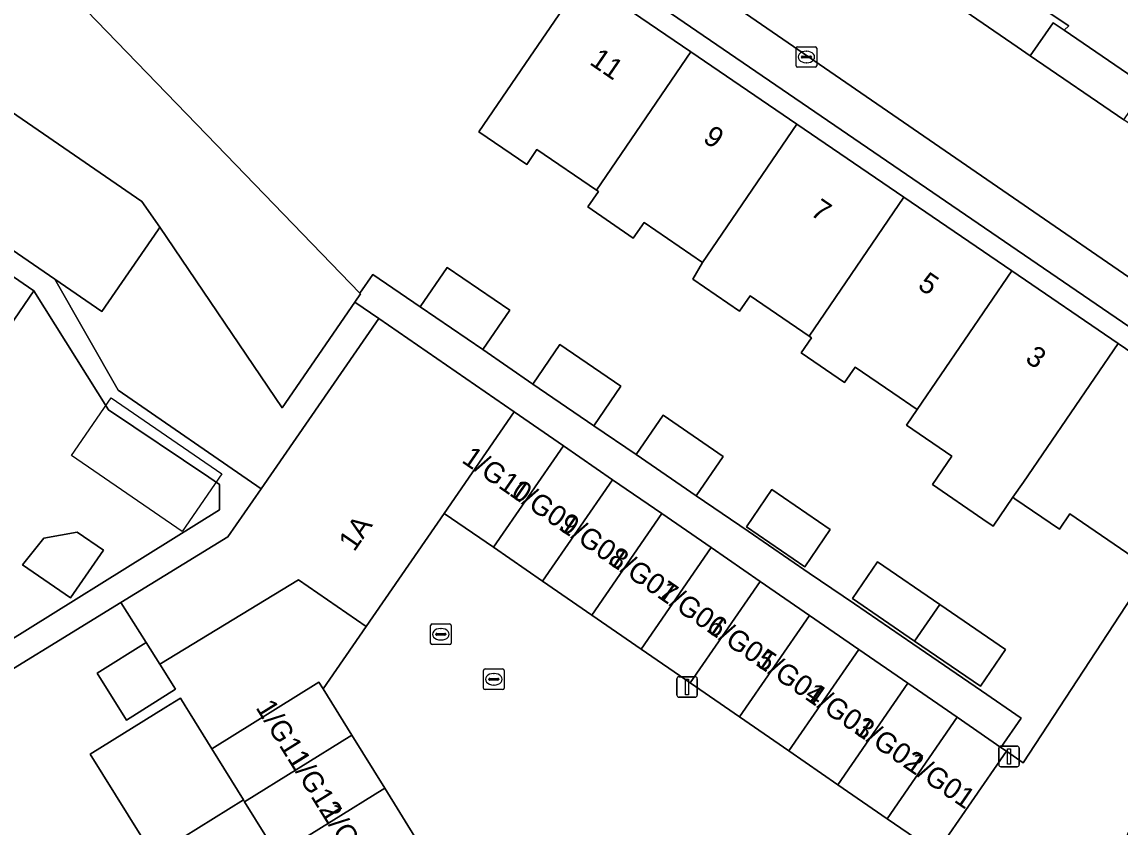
# Model space of a CAD drawing. Extents: x 160023 to 161302, y 384750 to 385707.
# Drawn here: x 160069.8 to 160123.2, y 385310.5 to 385349.6 of the extents above; entities that cross this region are included whole.
import ezdxf

# ---------------------------------------------------------------- set-up
doc = ezdxf.new("R2010")
doc.units = 0
for name, color, linetype in [('IMGEO_Erf', 7, 'Continuous'), ('IMGEO_Kolk', 7, 'Continuous'), ('IMGEO_Lichtmast', 7, 'Continuous'), ('IMGEO_Pand', 7, 'Continuous'), ('IMGEO_Pand_nummerreeks', 7, 'Continuous'), ('IMGEO_Pand_vergunning_verleend', 7, 'Continuous'), ('IMGEO_Rijbaan_lokaal_open', 7, 'Continuous'), ('IMGEO_Rioolput', 7, 'Continuous'), ('IMGEO_Voetpad_open', 7, 'Continuous')]:
    doc.layers.add(name, color=color, linetype=linetype)

msp = doc.modelspace()

# ---------------------------------------------------------------- linework, layer by layer
at = {"layer": 'IMGEO_Erf'}
for points in [[(160093.406, 385374.95), (160103.841, 385367.794), (160103.323, 385367.037), (160102.919, 385366.448), (160100.498, 385362.918), (160105.594, 385359.428), (160120.662, 385349.43), (160120.442, 385349.221), (160124.446, 385346.473), (160126.203, 385345.256), (160126.296, 385345.192), (160149.901, 385329.017), (160154.104, 385326.136), (160157.93, 385334.826), (160155.989, 385335.681), (160153.709, 385336.675), (160151.041, 385330.714), (160139.497, 385338.47), (160150.705, 385363.58)], [(160067.626, 385355.673), (160079.267, 385343.639), (160086.233, 385336.432), (160086.859, 385337.347), (160089.163, 385335.77), (160090.474, 385337.685), (160093.507, 385335.608), (160092.196, 385333.693), (160094.638, 385332.021), (160095.948, 385333.937), (160098.91, 385331.91), (160097.599, 385329.995), (160099.648, 385328.591), (160100.959, 385330.506), (160103.882, 385328.505), (160102.571, 385326.59), (160105.09, 385324.865), (160108.053, 385322.837), (160110.247, 385321.335), (160113.085, 385319.392), (160116.428, 385317.104), (160118.35, 385315.789), (160117.368, 385314.364), (160117.632, 385314.182), (160118.455, 385313.614), (160129.62, 385330.68), (160087.038, 385359.824)], [(160123.798, 385323.607), (160120.717, 385325.711), (160120.211, 385324.97), (160118.047, 385326.448), (160117.949, 385326.515), (160116.995, 385325.118), (160116.493, 385325.461), (160114.04, 385327.136), (160114.982, 385328.515), (160112.778, 385330.02), (160113.298, 385330.781), (160112.117, 385331.587), (160110.286, 385332.837), (160109.775, 385332.089), (160107.661, 385333.533), (160108.163, 385334.267), (160108.045, 385334.347), (160105.183, 385336.303), (160104.675, 385335.56), (160102.399, 385337.115), (160102.876, 385337.933), (160100.032, 385339.876), (160099.511, 385339.114), (160097.301, 385340.623), (160097.817, 385341.378), (160097.716, 385341.447), (160094.832, 385343.417), (160094.335, 385342.688), (160092.004, 385344.28), (160094.271, 385347.599), (160097.091, 385351.727), (160102.305, 385348.166), (160107.46, 385344.645), (160112.655, 385341.096), (160117.897, 385337.515), (160123.055, 385333.992), (160128.399, 385330.342)], [(160082.231, 385309.145), (160080.632, 385311.722), (160080.576, 385311.813), (160076.198, 385309.096), (160073.131, 385314.037), (160076.797, 385316.312), (160077.227, 385316.578), (160077.51, 385316.754), (160077.737, 385316.388), (160077.982, 385315.993), (160079.033, 385314.298), (160084.239, 385317.529), (160084.441, 385317.204), (160086.537, 385320.243), (160083.248, 385322.511), (160076.514, 385318.402), (160077.278, 385317.19), (160074.898, 385315.69), (160073.463, 385317.968), (160075.842, 385319.468), (160074.623, 385321.403), (160066.649, 385316.515)]]:
    msp.add_lwpolyline(points, dxfattribs=at)
for points in [[(160076.516, 385339.641), (160076.433, 385339.52), (160073.695, 385335.541), (160071.409, 385337.114), (160074.484, 385331.723), (160081.435, 385326.93), (160087.143, 385335.207), (160085.987, 385336.004), (160082.452, 385330.867)], [(160074.014, 385330.761), (160070.393, 385336.541), (160067.07, 385331.71), (160066.008, 385330.166), (160065.688, 385329.701), (160063.701, 385331.067), (160061.962, 385328.538), (160062.243, 385328.334), (160060.097, 385325.214), (160062.498, 385323.562), (160064.341, 385322.294), (160063.223, 385320.668), (160061.387, 385321.931), (160061.311, 385321.819), (160066.718, 385318.006), (160079.412, 385325.901), (160079.412, 385327.14), (160078.89, 385327.49)], [(160105.001, 385325.087), (160106.236, 385326.893), (160109.08, 385324.946), (160107.844, 385323.141)], [(160069.841, 385323.242), (160070.874, 385324.538), (160072.497, 385324.821), (160073.769, 385323.946), (160072.179, 385321.634)], [(160110.152, 385321.591), (160111.373, 385323.376), (160114.394, 385321.309), (160117.593, 385319.119), (160116.371, 385317.335), (160113.174, 385319.523)]]:
    msp.add_lwpolyline(points, close=True, dxfattribs=at)
at = {"layer": 'IMGEO_Kolk'}
for p, q in [((160107.417, 385347.485), (160107.417, 385348.337)), ((160107.492, 385348.411), (160108.344, 385348.411)), ((160107.905, 385348.191), (160107.93, 385348.191)), ((160108.418, 385348.337), (160108.418, 385347.485)), ((160107.676, 385347.905), (160107.676, 385347.917)), ((160108.114, 385347.868), (160107.716, 385347.868)), ((160107.719, 385347.954), (160108.117, 385347.954)), ((160107.928, 385347.631), (160107.903, 385347.631)), ((160108.16, 385347.917), (160108.16, 385347.905)), ((160108.344, 385347.411), (160107.492, 385347.411)), ((160092.235, 385317.248), (160092.235, 385318.1)), ((160092.31, 385318.174), (160093.162, 385318.174)), ((160092.723, 385317.954), (160092.748, 385317.954)), ((160093.236, 385318.1), (160093.236, 385317.248)), ((160092.494, 385317.668), (160092.494, 385317.68)), ((160092.932, 385317.631), (160092.534, 385317.631)), ((160092.537, 385317.717), (160092.935, 385317.717)), ((160092.746, 385317.394), (160092.721, 385317.394)), ((160092.978, 385317.68), (160092.978, 385317.668)), ((160093.162, 385317.174), (160092.31, 385317.174))]:
    msp.add_line(p, q, dxfattribs=at)
for points in [[(160107.417, 385347.485), (160107.417, 385348.337)], [(160107.492, 385348.411), (160108.344, 385348.411)], [(160108.418, 385348.337), (160108.418, 385347.485)], [(160108.344, 385347.411), (160107.492, 385347.411)], [(160092.235, 385317.248), (160092.235, 385318.1)], [(160092.31, 385318.174), (160093.162, 385318.174)], [(160093.236, 385318.1), (160093.236, 385317.248)], [(160093.162, 385317.174), (160092.31, 385317.174)]]:
    msp.add_lwpolyline(points, dxfattribs=at)
for centre, radius, start, end in [((160107.494, 385348.335), 0.0765, 91.552, 178.448), ((160107.494, 385348.335), 0.0765, 91.552, 178.448), ((160108.342, 385348.335), 0.0765, 1.552, 88.448), ((160108.342, 385348.335), 0.0765, 1.552, 88.448), ((160107.716, 385347.914), 0.0403, 85.8775, 175.7526), ((160107.713, 385347.904), 0.0366, 178.938, 274.7102), ((160108.117, 385347.911), 0.043, 264.8664, 352.4533), ((160108.121, 385347.916), 0.0386, 1.7309, 96.639), ((160107.494, 385347.487), 0.0765, 181.552, 268.448), ((160107.494, 385347.487), 0.0765, 181.552, 268.448), ((160108.342, 385347.487), 0.0765, 271.552, 358.448), ((160108.342, 385347.487), 0.0765, 271.552, 358.448), ((160092.312, 385318.098), 0.0765, 91.552, 178.448), ((160092.312, 385318.098), 0.0765, 91.552, 178.448), ((160093.16, 385318.098), 0.0765, 1.552, 88.448), ((160093.16, 385318.098), 0.0765, 1.552, 88.448), ((160092.312, 385317.25), 0.0765, 181.552, 268.448), ((160092.312, 385317.25), 0.0765, 181.552, 268.448), ((160092.534, 385317.677), 0.0403, 85.8775, 175.7526), ((160092.531, 385317.667), 0.0366, 178.938, 274.7102), ((160092.935, 385317.674), 0.043, 264.8664, 352.4533), ((160092.939, 385317.679), 0.0386, 1.7309, 96.639), ((160093.16, 385317.25), 0.0765, 271.552, 358.448), ((160093.16, 385317.25), 0.0765, 271.552, 358.448)]:
    msp.add_arc(centre, radius, start, end, dxfattribs=at)
for centre, major_axis, ratio, start_param, end_param in [((160107.904, 385347.911), (-0.387, 0.002), 0.722429, 4.712389, 7.853982), ((160107.929, 385347.911), (-0.39, 0.002), 0.717154, 1.570796, 4.712389), ((160092.722, 385317.674), (-0.387, 0.002), 0.722429, 4.712389, 7.853982), ((160092.747, 385317.674), (-0.39, 0.002), 0.717154, 1.570796, 4.712389)]:
    msp.add_ellipse(centre, major_axis=major_axis, ratio=ratio, start_param=start_param, end_param=end_param, dxfattribs=at)
at = {"layer": 'IMGEO_Lichtmast'}
for p, q in [((160101.726, 385317.8), (160102.516, 385317.8)), ((160102.516, 385317.8), (160101.726, 385317.8)), ((160101.626, 385316.9), (160101.626, 385317.7)), ((160101.626, 385317.7), (160101.626, 385316.9)), ((160102.616, 385317.7), (160102.616, 385316.9)), ((160102.616, 385316.9), (160102.616, 385317.7)), ((160102.516, 385316.8), (160101.726, 385316.8)), ((160101.726, 385316.8), (160102.516, 385316.8)), ((160117.264, 385313.526), (160117.264, 385314.326)), ((160117.264, 385314.326), (160117.264, 385313.526)), ((160117.364, 385314.426), (160118.154, 385314.426)), ((160118.154, 385314.426), (160117.364, 385314.426)), ((160118.254, 385314.326), (160118.254, 385313.526)), ((160118.254, 385313.526), (160118.254, 385314.326)), ((160118.154, 385313.426), (160117.364, 385313.426)), ((160117.364, 385313.426), (160118.154, 385313.426))]:
    msp.add_line(p, q, dxfattribs=at)
for points in [[(160102.046, 385317.675), (160102.196, 385317.675), (160102.196, 385316.925), (160102.046, 385316.925), (160102.046, 385317.675)], [(160117.684, 385314.301), (160117.834, 385314.301), (160117.834, 385313.551), (160117.684, 385313.551), (160117.684, 385314.301)]]:
    msp.add_lwpolyline(points, dxfattribs=at)
for centre, start, end in [((160101.726, 385317.7), 90, 180), ((160101.726, 385317.7), 90, 180), ((160102.516, 385317.7), 0, 90), ((160102.516, 385317.7), 360, 90), ((160101.726, 385316.9), 180, 270), ((160101.726, 385316.9), 180, 270), ((160102.516, 385316.9), 270, 0), ((160102.516, 385316.9), 270, 0), ((160117.364, 385314.326), 90, 180), ((160117.364, 385314.326), 90, 180), ((160118.154, 385314.326), 0, 90), ((160118.154, 385314.326), 360, 90), ((160117.364, 385313.526), 180, 270), ((160117.364, 385313.526), 180, 270), ((160118.154, 385313.526), 270, 0), ((160118.154, 385313.526), 270, 0)]:
    msp.add_arc(centre, 0.1, start, end, dxfattribs=at)
at = {"layer": 'IMGEO_Pand'}
for points in [[(160067.626, 385355.673), (160066.087, 385356.732), (160064.953, 385355.085), (160064.023, 385355.726), (160063.16, 385354.418), (160064.066, 385353.794), (160061.755, 385350.435), (160075.631, 385340.89), (160076.516, 385339.641), (160082.452, 385330.867), (160085.987, 385336.004), (160086.261, 385336.403), (160086.233, 385336.432), (160079.267, 385343.639)], [(160092.004, 385344.28), (160094.335, 385342.688), (160094.832, 385343.417), (160097.716, 385341.447), (160102.305, 385348.166), (160097.091, 385351.727), (160094.271, 385347.599)], [(160061.755, 385350.435), (160058.636, 385345.901), (160062.756, 385343.067), (160071.409, 385337.114), (160073.695, 385335.541), (160076.433, 385339.52), (160076.516, 385339.641), (160075.631, 385340.89)], [(160097.817, 385341.378), (160097.301, 385340.623), (160099.511, 385339.114), (160100.032, 385339.876), (160102.876, 385337.933), (160107.46, 385344.645), (160102.305, 385348.166), (160097.716, 385341.447)], [(160064.647, 385333.377), (160067.07, 385331.71), (160070.393, 385336.541), (160062.163, 385342.203), (160058.043, 385345.037), (160057.702, 385344.542), (160056.923, 385344.603), (160055.778, 385342.939), (160056.123, 385342.214), (160054.852, 385340.366), (160062.091, 385335.135)], [(160102.399, 385337.115), (160104.675, 385335.56), (160105.183, 385336.303), (160108.045, 385334.347), (160112.655, 385341.096), (160107.46, 385344.645), (160102.876, 385337.933)], [(160117.897, 385337.515), (160112.655, 385341.096), (160108.045, 385334.347), (160108.163, 385334.267), (160107.661, 385333.533), (160109.775, 385332.089), (160110.286, 385332.837), (160112.117, 385331.587), (160113.298, 385330.781)], [(160089.163, 385335.77), (160092.196, 385333.693), (160093.507, 385335.608), (160090.474, 385337.685)], [(160123.055, 385333.992), (160117.897, 385337.515), (160113.298, 385330.781), (160112.778, 385330.02), (160114.982, 385328.515), (160114.04, 385327.136), (160116.493, 385325.461), (160116.995, 385325.118), (160117.949, 385326.515), (160118.457, 385327.259)], [(160090.326, 385325.736), (160093.727, 385330.667), (160087.143, 385335.207), (160081.435, 385326.93), (160079.822, 385324.59), (160074.623, 385321.403), (160075.842, 385319.468), (160076.514, 385318.402), (160083.248, 385322.511), (160086.537, 385320.243)], [(160094.638, 385332.021), (160097.599, 385329.995), (160098.91, 385331.91), (160095.948, 385333.937)], [(160128.399, 385330.342), (160123.055, 385333.992), (160118.457, 385327.259), (160117.949, 385326.515), (160118.047, 385326.448), (160120.211, 385324.97), (160120.717, 385325.711), (160123.798, 385323.607), (160125.58, 385326.215)], [(160092.716, 385324.087), (160096.117, 385329.018), (160093.727, 385330.667), (160090.326, 385325.736)], [(160099.648, 385328.591), (160102.571, 385326.59), (160103.882, 385328.505), (160100.959, 385330.506)], [(160092.716, 385324.087), (160095.107, 385322.439), (160098.508, 385327.37), (160096.117, 385329.018)], [(160095.107, 385322.439), (160097.498, 385320.79), (160100.898, 385325.721), (160098.508, 385327.37)], [(160105.001, 385325.087), (160107.844, 385323.141), (160109.08, 385324.946), (160106.236, 385326.893)], [(160103.289, 385324.073), (160100.898, 385325.721), (160097.498, 385320.79), (160099.888, 385319.142)], [(160069.841, 385323.242), (160072.179, 385321.634), (160073.769, 385323.946), (160072.497, 385324.821), (160070.874, 385324.538)], [(160099.888, 385319.142), (160102.278, 385317.493), (160105.679, 385322.424), (160103.289, 385324.073)], [(160113.174, 385319.523), (160114.394, 385321.309), (160111.373, 385323.376), (160110.152, 385321.591)], [(160108.07, 385320.776), (160105.679, 385322.424), (160102.278, 385317.493), (160104.669, 385315.844)], [(160114.394, 385321.309), (160113.174, 385319.523), (160116.371, 385317.335), (160117.593, 385319.119)], [(160104.669, 385315.844), (160107.06, 385314.196), (160110.461, 385319.127), (160108.07, 385320.776)], [(160076.514, 385318.402), (160075.842, 385319.468), (160073.463, 385317.968), (160074.898, 385315.69), (160077.278, 385317.19)], [(160112.851, 385317.479), (160110.461, 385319.127), (160107.06, 385314.196), (160109.45, 385312.547)], [(160085.838, 385314.953), (160084.441, 385317.204), (160084.239, 385317.529), (160079.033, 385314.298), (160080.576, 385311.813), (160080.632, 385311.722)], [(160109.45, 385312.547), (160111.84, 385310.899), (160115.242, 385315.83), (160112.851, 385317.479)], [(160080.576, 385311.813), (160079.033, 385314.298), (160077.982, 385315.993), (160077.737, 385316.388), (160077.51, 385316.754), (160077.227, 385316.578), (160076.797, 385316.312), (160073.131, 385314.037), (160076.198, 385309.096)], [(160117.632, 385314.182), (160117.368, 385314.364), (160115.242, 385315.83), (160111.84, 385310.899), (160114.231, 385309.25)], [(160080.632, 385311.722), (160082.231, 385309.145), (160087.437, 385312.376), (160085.838, 385314.953)], [(160082.231, 385309.145), (160083.83, 385306.569), (160089.036, 385309.8), (160087.437, 385312.376)]]:
    msp.add_lwpolyline(points, close=True, dxfattribs=at)
at = {"layer": 'IMGEO_Pand_vergunning_verleend'}
msp.add_lwpolyline([(160074.152, 385331.348), (160079.528, 385327.65), (160077.601, 385324.849), (160072.225, 385328.547)], close=True, dxfattribs=at)
at = {"layer": 'IMGEO_Rijbaan_lokaal_open'}
for points in [[(160154.329, 385323.627), (160153.286, 385324.341), (160123.334, 385344.855), (160118.796, 385347.963), (160118.151, 385348.405), (160076.337, 385377.118), (160072.906, 385372.103), (160130.948, 385332.139), (160134.348, 385329.812), (160152.796, 385317.185)], [(160120.909, 385304.204), (160128.791, 385322.11), (160132.92, 385328.421), (160129.854, 385330.52), (160129.62, 385330.68), (160118.455, 385313.614), (160117.632, 385314.182), (160114.231, 385309.25), (160111.84, 385310.899), (160109.45, 385312.547), (160107.06, 385314.196), (160104.669, 385315.844), (160102.278, 385317.493), (160099.888, 385319.142), (160097.498, 385320.79), (160095.107, 385322.439), (160092.716, 385324.087), (160090.326, 385325.736), (160086.537, 385320.243), (160084.441, 385317.204), (160085.838, 385314.953), (160087.437, 385312.376), (160089.036, 385309.8)]]:
    msp.add_lwpolyline(points, dxfattribs=at)
at = {"layer": 'IMGEO_Rioolput'}
for p, q in [((160089.662, 385319.436), (160089.662, 385320.288)), ((160089.737, 385320.362), (160090.589, 385320.362)), ((160089.964, 385319.905), (160090.362, 385319.905)), ((160090.15, 385320.142), (160090.175, 385320.142)), ((160090.663, 385320.288), (160090.663, 385319.436)), ((160090.589, 385319.362), (160089.737, 385319.362)), ((160089.921, 385319.856), (160089.921, 385319.868)), ((160090.359, 385319.819), (160089.961, 385319.819)), ((160090.173, 385319.582), (160090.148, 385319.582)), ((160090.405, 385319.868), (160090.405, 385319.856))]:
    msp.add_line(p, q, dxfattribs=at)
for points in [[(160089.662, 385319.436), (160089.662, 385320.288)], [(160089.737, 385320.362), (160090.589, 385320.362)], [(160090.663, 385320.288), (160090.663, 385319.436)], [(160090.589, 385319.362), (160089.737, 385319.362)]]:
    msp.add_lwpolyline(points, dxfattribs=at)
for centre, radius, start, end in [((160089.739, 385320.286), 0.0765, 91.552, 178.448), ((160089.739, 385320.286), 0.0765, 91.552, 178.448), ((160089.961, 385319.865), 0.0403, 85.8775, 175.7526), ((160090.366, 385319.867), 0.0386, 1.7309, 96.639), ((160090.587, 385320.286), 0.0765, 1.552, 88.448), ((160090.587, 385320.286), 0.0765, 1.552, 88.448), ((160089.739, 385319.438), 0.0765, 181.552, 268.448), ((160089.739, 385319.438), 0.0765, 181.552, 268.448), ((160089.958, 385319.855), 0.0366, 178.938, 274.7102), ((160090.362, 385319.862), 0.043, 264.8664, 352.4533), ((160090.587, 385319.438), 0.0765, 271.552, 358.448), ((160090.587, 385319.438), 0.0765, 271.552, 358.448)]:
    msp.add_arc(centre, radius, start, end, dxfattribs=at)
for centre, major_axis, ratio, start_param, end_param in [((160090.149, 385319.862), (-0.387, 0.002), 0.722429, 4.712389, 7.853982), ((160090.174, 385319.862), (-0.39, 0.002), 0.717154, 1.570796, 4.712389)]:
    msp.add_ellipse(centre, major_axis=major_axis, ratio=ratio, start_param=start_param, end_param=end_param, dxfattribs=at)
at = {"layer": 'IMGEO_Voetpad_open'}
for points in [[(160084.795, 385373.675), (160085.346, 385374.478), (160080.847, 385377.563), (160080.615, 385377.224), (160080.343, 385377.411), (160080.573, 385377.746), (160077.873, 385379.652), (160077.235, 385380.103), (160076.337, 385377.118), (160118.151, 385348.405), (160118.796, 385347.963), (160119.906, 385349.578), (160120.442, 385349.221), (160120.662, 385349.43), (160105.594, 385359.428), (160100.498, 385362.918)], [(160072.906, 385372.103), (160071.027, 385370.783), (160071.709, 385370.322), (160074.263, 385368.593), (160081.559, 385363.574), (160087.038, 385359.824), (160129.62, 385330.68), (160129.854, 385330.52), (160130.948, 385332.139)], [(160118.796, 385347.963), (160123.334, 385344.855), (160124.446, 385346.473), (160120.442, 385349.221), (160119.906, 385349.578)], [(160102.571, 385326.59), (160099.648, 385328.591), (160097.599, 385329.995), (160094.638, 385332.021), (160092.196, 385333.693), (160089.163, 385335.77), (160086.859, 385337.347), (160086.233, 385336.432), (160086.261, 385336.403), (160085.987, 385336.004), (160087.143, 385335.207), (160093.727, 385330.667), (160096.117, 385329.018), (160098.508, 385327.37), (160100.898, 385325.721), (160103.289, 385324.073), (160105.679, 385322.424), (160108.07, 385320.776), (160110.461, 385319.127), (160112.851, 385317.479), (160115.242, 385315.83), (160117.368, 385314.364), (160118.35, 385315.789), (160116.428, 385317.104), (160113.085, 385319.392), (160110.247, 385321.335), (160108.053, 385322.837), (160105.09, 385324.865)]]:
    msp.add_lwpolyline(points, close=True, dxfattribs=at)
for points in [[(160066.649, 385316.515), (160074.623, 385321.403), (160079.822, 385324.59), (160081.435, 385326.93), (160074.484, 385331.723), (160071.409, 385337.114), (160062.756, 385343.067)], [(160062.163, 385342.203), (160070.393, 385336.541), (160074.014, 385330.761), (160078.89, 385327.49), (160079.412, 385327.14), (160079.412, 385325.901), (160066.718, 385318.006)]]:
    msp.add_lwpolyline(points, dxfattribs=at)

# ---------------------------------------------------------------- texts
at = {"layer": 'IMGEO_Pand_nummerreeks'}
for s, rotation, p in [('11', 325.6649, (160097.337, 385347.586)), ('9', 325.6649, (160102.841, 385343.828)), ('7', 325.6649, (160108.059, 385340.264)), ('5', 325.6626, (160113.277, 385336.7)), ('3', 325.6626, (160118.495, 385333.136)), ('1/G10', 325.408, (160091.13, 385328.243)), ('1/G09', 325.408, (160093.44, 385326.649)), ('1A', 55.405, (160085.952, 385323.833)), ('1/G08', 325.408, (160095.836, 385324.997)), ('1/G07', 325.408, (160098.224, 385323.35)), ('1/G06', 325.408, (160100.614, 385321.702)), ('1/G05', 325.408, (160103.005, 385320.053)), ('1/G04', 325.408, (160105.395, 385318.405)), ('1/G03', 325.408, (160107.786, 385316.756)), ('1/G11', 301.8276, (160081.142, 385316.3)), ('1/G02', 325.408, (160110.171, 385315.111)), ('1/G12', 301.8248, (160082.679, 385313.823)), ('1/G01', 325.4105, (160112.657, 385313.396)), ('1/G13', 301.8248, (160084.281, 385311.242))]:
    msp.add_text(s, height=1, rotation=rotation, dxfattribs=at).set_placement(p)

doc.saveas('drawing.dxf')
